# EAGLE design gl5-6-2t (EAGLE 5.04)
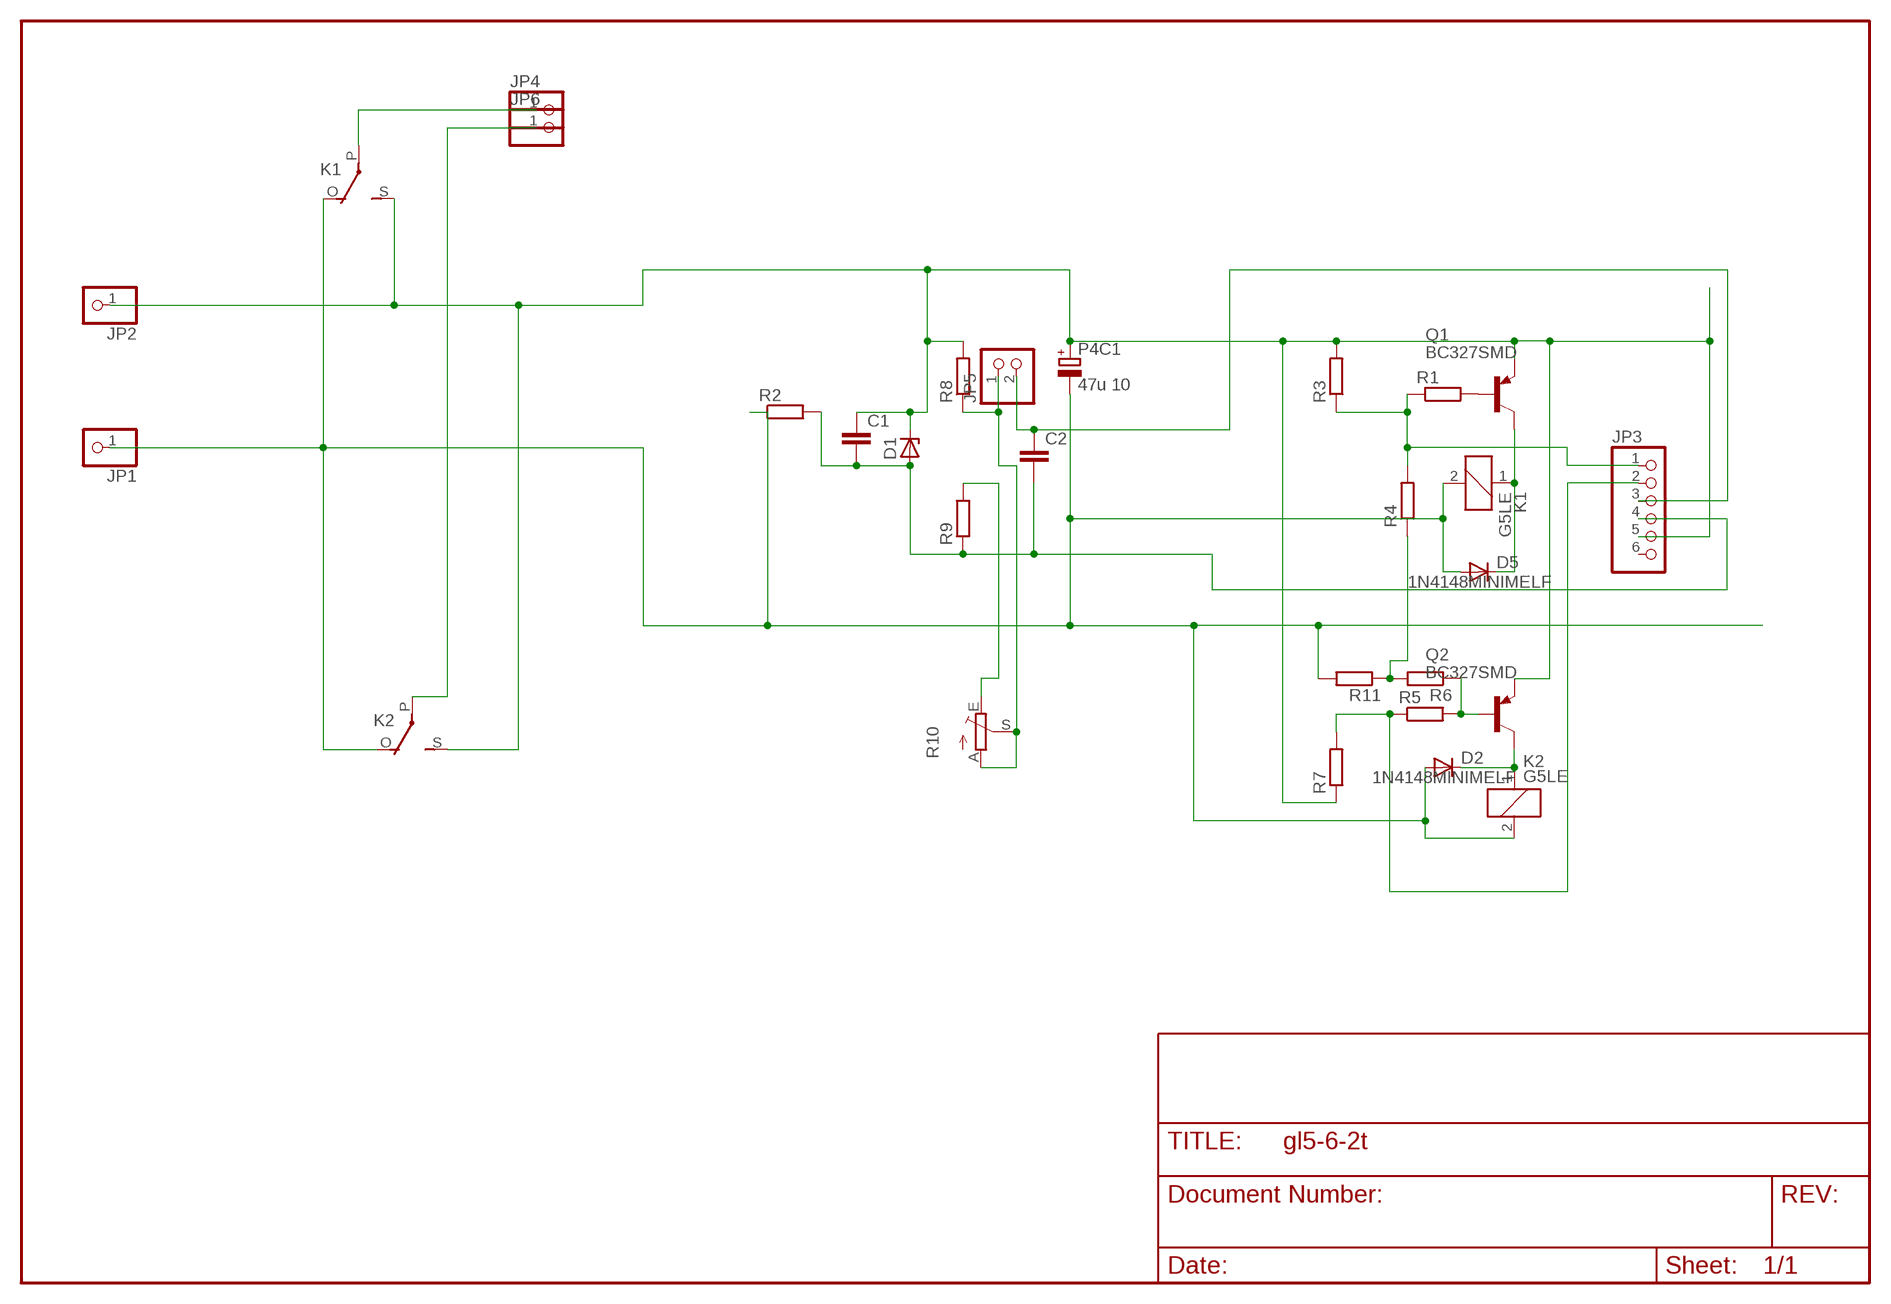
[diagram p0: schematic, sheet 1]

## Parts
C1  C-EUC1206  [C1206]
C2  C-EUC1206  [C1206]
D1  ZENER-DIODESOT23  [SOT23]
D2  1N4148MINIMELF  [MINIMELF]
D5  1N4148MINIMELF  [MINIMELF]
JP1  PINHD-1X1  [1X01]
JP2  PINHD-1X1  [1X01]
JP3  PINHD-1X6  [1X06]
JP4  PINHD-1X1  [1X01]
JP5  PINHD-1X2  [1X02]
JP6  PINHD-1X1  [1X01]
K1  G5LE  [G5LE]
K2  G5LE  [G5LE]
P4C1  47u 10  CPOL-EUE2-5  [E2-5]
Q1  BC327SMD  [SOT23-BEC]
Q2  BC327SMD  [SOT23-BEC]
R1  R-EU_R0805  [R0805]
R2  R-EU_R0805  [R0805]
R3  R-EU_R0805  [R0805]
R4  R-EU_R1210  [R1210]
R5  R-EU_R0805  [R0805]
R6  R-EU_R1210  [R1210]
R7  R-EU_R0805  [R0805]
R8  R-EU_R0805  [R0805]
R9  R-EU_R0805  [R0805]
R10  TRIM_EU-CA6V  [CA6V]
R11  R-EU_R0805  [R0805]

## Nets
N$1: R9.2 R10.E
N$2: JP4.1 K1.P(2:P)
N$3: JP5.1 R8.1 R10.A R10.S
N$4: JP6.1 K2.P(2:P)
N$5: C1.2 C2.2 D1.1(A) JP3.4 R2.2 R9.1
N$6: R4.1 R6.2 R11.1
N$7: C2.1 JP3.3 JP5.2
N$8: Q1.B R1.2
N$10: JP3.1 R1.1 R3.1 R4.2
N$11: D5.C K1.1 Q1.C
N$12: D2.C K2.1 Q2.C
N$13: JP3.2 R5.1 R7.2
N$15: Q2.B R5.2 R6.1
V+: C1.1 D1.3(C) JP2.1 JP3.5 K1.S(2:S) K2.S(2:S) P4C1.+ Q1.E Q2.E R3.2 R7.1 R8.2
V-: D2.A D5.A JP1.1 K1.2 K1.O(2:O) K2.2 K2.O(2:O) P4C1.- R2.1 R11.2
Unconnected: JP3.6

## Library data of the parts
C1 C2 = rcl-2:C-EU: CAPACITOR, European symbol
D1 = diode-1:ZENER-DIODE: Z-Diode
D2 D5 = diode-1:1N4148: DIODE
JP1 JP2 JP4 JP6 = pinhead(2):PINHD-1X1: PIN HEADER
JP3 = pinhead:PINHD-1X6: PIN HEADER
JP5 = pinhead:PINHD-1X2: PIN HEADER
K1 K2 = relay:G5LE: RELAY 1 x switch, 10 A/120 V AC, 8 A/30 V DC, Omron
P4C1 = rcl:CPOL-EU: POLARIZED CAPACITOR, European symbol
Q1 Q2 = transistor-pnp:BC327*: PNP Transistror
R1-R9 R11 = rcl-2:R-EU_: RESISTOR, European symbol
R10 = pot:TRIM_EU-: POTENTIOMETER

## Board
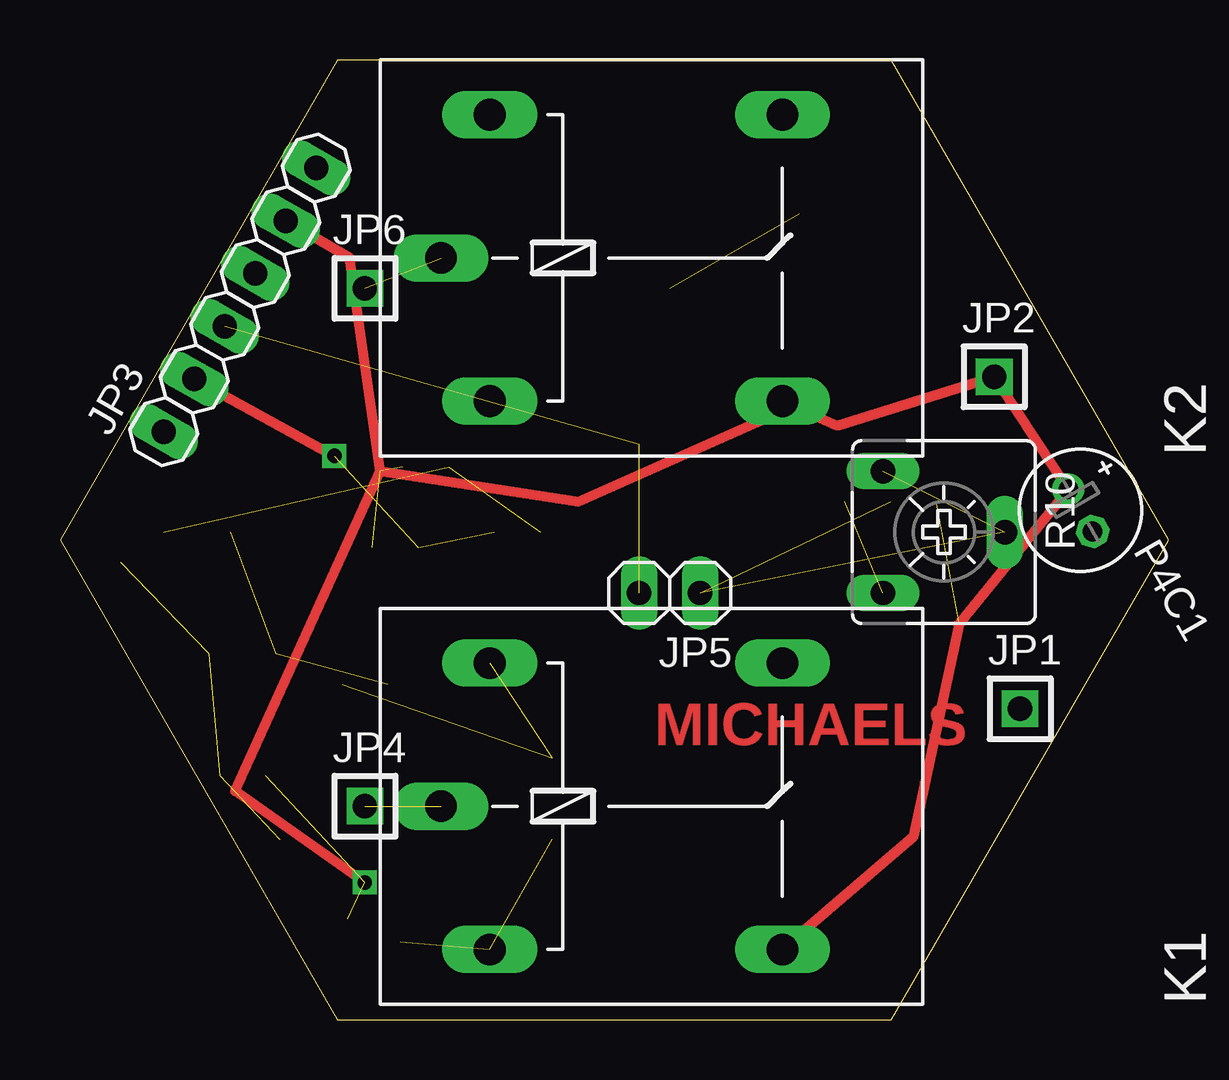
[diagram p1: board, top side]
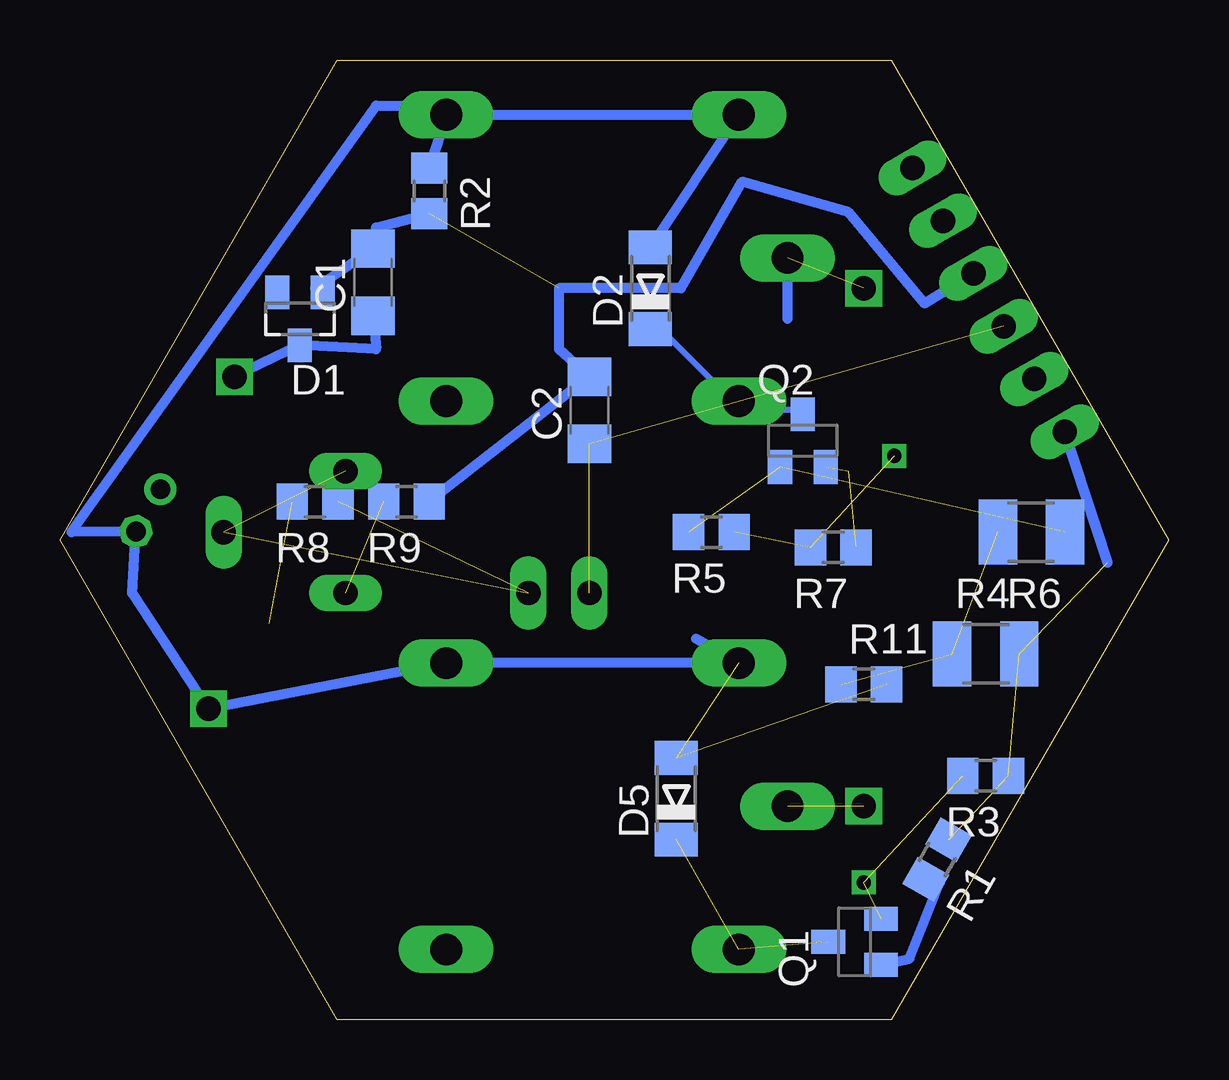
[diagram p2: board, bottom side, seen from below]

Size 46.19 x 40 mm. Coordinates in mm from the lower left corner, seen from the top.
Outline: 11.55,0 34.64,0 46.19,20 34.64,40 11.55,40 0,20 11.55,0
Copper layers (1*16): Top 0.035mm / dielectric 1.5mm / Bottom 0.035mm
Design rules "default": minimum track width 10mil, minimum drill 24mil, track to track 8mil, track to pad 8mil, pad to pad 8mil, via to via 8mil, smd to smd 8mil, copper to edge 40mil, drill to drill 8mil, minimum pad ring 10mil, minimum via ring 8mil, stop-mask expansion 4mil, vias tented up to drill 0mil, thermal gap 10mil

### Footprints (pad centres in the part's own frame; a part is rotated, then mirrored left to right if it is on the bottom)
C1206 = smd 1.6 x 1.8: 1 -1.4,0; 2 1.4,0
SOT23 = smd 1 x 1.4: 1 -0.95,-1.1; 2 0.95,-1.1; 3 0,1.1
MINIMELF = smd 1.4 x 1.8: A 1.7,0; C -1.7,0
1X01 = drill 1.016 square: 1 0,0
1X06 = drill 1.016 long: 1 -6.35,0; 2 -3.81,0; 3 -1.27,0; 4 1.27,0; 5 3.81,0; 6 6.35,0
1X02 = drill 1.016 long: 1 -1.27,0; 2 1.27,0
G5LE = drill 1.321 long: 1 -7.493,-5.969; 2 -7.493,5.969; O 4.699,5.969; P -9.525,0; S 4.699,-5.969
E2-5 = drill 0.813 pad 1.27 round: + -1.016,0 | drill 0.813 pad 1.27 octagon: - 1.016,0
SOT23-BEC = smd 1 x 1.4: B -0.95,-1.1; C 0,1.1; E 0.95,-1.1
R0805 = smd 1.3 x 1.5: 1 -0.95,0; 2 0.95,0
R1210 = smd 1.6 x 2.7: 1 -1.4,0; 2 1.4,0
CA6V = drill 1.016 long: A -2.54,-2.54; E 2.54,-2.54; S 0,2.54

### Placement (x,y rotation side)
C1  33.15,30.73 90 bottom
C2  24.13,25.4 90 bottom
D1  36.2,29.21 180 bottom
D2  21.59,30.48 90 bottom
D5  20.51,9.21 90 bottom
JP1  40.01,12.95 0 top
JP2  38.93,26.8 0 top
JP3  7.5,30 60 top
JP4  12.7,8.89 0 top
JP5  25.4,17.78 180 top
JP6  12.7,30.48 0 top
K1  25.4,8.89 0 top
K2  25.4,31.75 0 top
P4C1  42.52,21.22 300 top
Q1  13.08,3.24 90 bottom
Q2  15.24,24.13 0 bottom
R1  9.64,6.67 240 bottom
R2  30.8,34.54 270 bottom
R3  7.62,10.16 180 bottom
R4  7.62,15.24 0 bottom
R5  19.05,20.32 180 bottom
R6  5.71,20.32 180 bottom
R7  13.97,19.68 180 bottom
R8  35.56,21.59 180 bottom
R9  31.75,21.59 180 bottom
R10  36.83,20.32 270 top
R11  12.7,13.97 0 bottom

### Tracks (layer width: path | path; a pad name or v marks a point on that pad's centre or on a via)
N$1  (1 unrouted)
N$2  (1 unrouted)
N$3  (3 unrouted)
N$4  (1 unrouted)
  Bottom 0.406: 15.88,29.21 K2.P
N$5  (1 unrouted)
  Bottom 0.406: R2.2 33.02,33.02 C1.2 35.56,30.48 D1.1 | JP3.4 10.16,29.84 13.34,33.66 17.78,34.92 20.32,30.48 25.4,30.48 25.4,27.94 C2.2 R9.1
N$6  (2 unrouted)
N$7  (2 unrouted)
N$8
  Bottom 0.406: Q1.B 10.79,2.54 9.53,5.71 R1.2
N$10  (3 unrouted)
  Bottom 0.406: 2.54,19.05 JP3.1
N$11  (2 unrouted)
N$12
  Bottom 0.254: Q2.C 15.24,25.4 16.51,25.4 K2.1 19.05,26.67 21.59,29.21 D2.C
N$13  (via drill 0.6)  (2 unrouted)
  Top 0.406: JP3.2 v11.43,23.5
N$15  (2 unrouted)
V+  (via drill 0.6)  (5 unrouted)
  Top 0.406: K1.S 35.56,7.62 37.47,16.51 P4C1.+ JP2.1 32.38,24.77 30.56,25.58 | 30.56,25.58 K2.S | JP3.5 12.06,31.75 13.34,22.86 | 13.34,22.86 21.59,21.59 30.56,25.58 | v12.7,5.71 7.3,9.53 13.34,22.86
  Bottom 0.406: JP2.1 D1.3 33.02,27.94 C1.1
V-  (2 unrouted)
  Bottom 0.406: 19.68,15.88 K1.2 K1.O JP1.1 43.18,17.78 P4C1.- 45.72,20.32 33.02,38.1 30.48,38.1 K2.O | K2.O K2.2 D2.A | K2.O R2.1

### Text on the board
Top: MICHAELS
